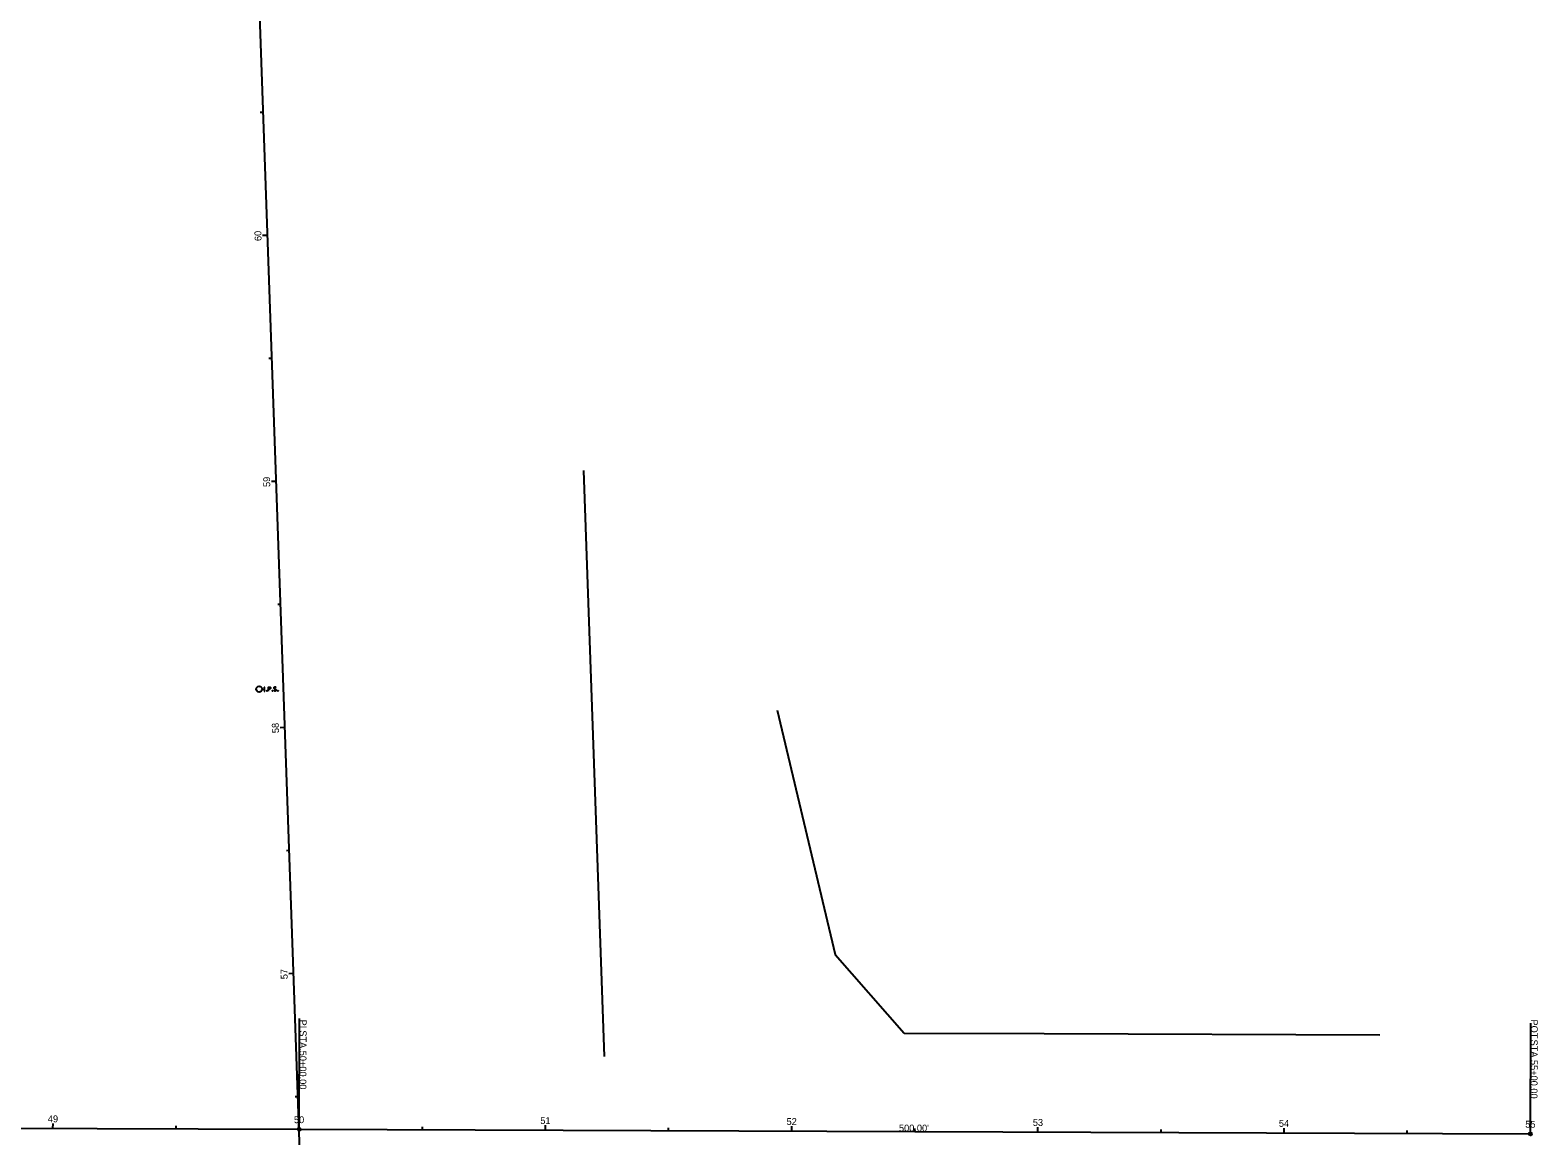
# Model space of a CAD drawing. Extents: x 146022 to 147490, y 436269 to 440659.
# Drawn here: x 146878 to 147490, y 438626 to 439075 of the extents above; entities that cross this region are included whole.
import ezdxf

# ---------------------------------------------------------------- set-up
doc = ezdxf.new("R2010")
doc.units = 0
for name, color, linetype in [('GE_X_Alignment', 7, 'Continuous'), ('GE_X_Alignment_100_Cardinal_Points', 7, 'Continuous'), ('GE_X_Alignment_100_Distances', 7, 'Continuous'), ('GE_X_Alignment_100_Stations', 7, 'Continuous'), ('RW_X_CL', 7, 'Continuous'), ('RW_X_CL_100_Stations', 7, 'Continuous'), ('RW_X_Esmt_SH', 7, 'Continuous'), ('RW_X_Fee_WL', 7, 'Continuous'), ('SV_P_Mon_Cells_Set', 7, 'Continuous')]:
    doc.layers.add(name, color=color, linetype=linetype)

msp = doc.modelspace()

# ---------------------------------------------------------------- linework, layer by layer
at = {"layer": 'GE_X_Alignment'}
for p, q in [((146487.13, 438630.33), (146987.13, 438628.49)), ((146987.13, 438628.49), (147487.13, 438626.65))]:
    msp.add_line(p, q, dxfattribs=at)
at = {"layer": 'GE_X_Alignment_100_Cardinal_Points'}
for p, q in [((146987.13, 438628.49), (146987.3, 438673.49)), ((147487.13, 438626.65), (147487.29, 438671.64))]:
    msp.add_line(p, q, dxfattribs=at)
for centre in [(146987.13, 438628.49), (147487.13, 438626.65)]:
    msp.add_circle(centre, 0.6, dxfattribs=at)
at = {"layer": 'GE_X_Alignment_100_Stations'}
for p, q in [((146887.13, 438628.86), (146887.14, 438630.86)), ((146937.13, 438628.67), (146937.13, 438629.87)), ((146987.13, 438628.49), (146987.14, 438630.49)), ((147037.13, 438628.3), (147037.13, 438629.5)), ((147087.13, 438628.12), (147087.14, 438630.12)), ((147137.13, 438627.93), (147137.13, 438629.13)), ((147187.13, 438627.75), (147187.14, 438629.75)), ((147287.13, 438627.38), (147287.13, 438629.38)), ((147387.13, 438627.01), (147387.13, 438629.01)), ((147237.13, 438627.57), (147237.13, 438628.77)), ((147337.13, 438627.2), (147337.13, 438628.4)), ((147437.13, 438626.83), (147437.13, 438628.03)), ((147487.13, 438626.65), (147487.13, 438628.65))]:
    msp.add_line(p, q, dxfattribs=at)
at = {"layer": 'RW_X_CL'}
msp.add_line((147030.73, 437397.38), (146946.25, 439782.71), dxfattribs=at)
at = {"layer": 'RW_X_CL_100_Stations'}
for p, q in [((146972.5, 439041.5), (146971.3, 439041.46)), ((146974.27, 438991.53), (146972.27, 438991.46)), ((146976.04, 438941.56), (146974.84, 438941.52)), ((146977.81, 438891.59), (146975.81, 438891.52)), ((146979.58, 438841.62), (146978.38, 438841.58)), ((146981.35, 438791.66), (146979.35, 438791.58)), ((146983.12, 438741.69), (146981.92, 438741.64)), ((146984.89, 438691.72), (146982.89, 438691.65)), ((146986.66, 438641.75), (146985.46, 438641.71))]:
    msp.add_line(p, q, dxfattribs=at)
at = {"layer": 'RW_X_Esmt_SH'}
for p, q in [((147181.23, 438798.73), (147204.75, 438699.5)), ((147204.75, 438699.5), (147232.84, 438667.58)), ((147232.84, 438667.58), (147289.66, 438667.37)), ((147289.66, 438667.37), (147426.01, 438666.87))]:
    msp.add_line(p, q, dxfattribs=at)
at = {"layer": 'RW_X_Fee_WL'}
msp.add_line((147111.16, 438658.03), (147102.73, 438896.02), dxfattribs=at)
at = {"layer": 'SV_P_Mon_Cells_Set'}
for points in [[(146972.87, 438808.08), (146973.22, 438808.08)], [(146972.87, 438806.48), (146973.22, 438806.48)], [(146973.04, 438806.48), (146973.04, 438808.08)], [(146974, 438806.7), (146974.06, 438806.7), (146974.09, 438806.67), (146974.12, 438806.62), (146974.12, 438806.56), (146974.09, 438806.51), (146974.06, 438806.48), (146974, 438806.48), (146973.97, 438806.51), (146973.94, 438806.56), (146973.94, 438806.62), (146973.97, 438806.67), (146974, 438806.7)], [(146974.61, 438806.48), (146974.61, 438808.08), (146975.14, 438808.08), (146975.19, 438808.07), (146975.27, 438808.05), (146975.3, 438808.02), (146975.34, 438808), (146975.38, 438807.93), (146975.41, 438807.87), (146975.44, 438807.77), (146975.44, 438807.62), (146975.42, 438807.57), (146975.4, 438807.49), (146975.36, 438807.4), (146975.31, 438807.37), (146975.28, 438807.34), (146975.23, 438807.32), (146975.14, 438807.3), (146974.61, 438807.3)], [(146976.25, 438806.7), (146976.31, 438806.7), (146976.34, 438806.67), (146976.37, 438806.62), (146976.37, 438806.56), (146976.34, 438806.51), (146976.31, 438806.48), (146976.25, 438806.48), (146976.22, 438806.51), (146976.18, 438806.56), (146976.18, 438806.62), (146976.22, 438806.67), (146976.25, 438806.7)], [(146977.62, 438807.97), (146977.6, 438808), (146977.56, 438808.02), (146977.46, 438808.06), (146977.34, 438808.08), (146977.25, 438808.08), (146977.22, 438808.08), (146977.08, 438808.05), (146976.96, 438807.97), (146976.88, 438807.87), (146976.86, 438807.77), (146976.86, 438807.69), (146976.88, 438807.59), (146976.97, 438807.5), (146977.57, 438807.13), (146977.63, 438807.08), (146977.65, 438807.03), (146977.67, 438806.95), (146977.67, 438806.87), (146977.66, 438806.8), (146977.65, 438806.75), (146977.63, 438806.69), (146977.61, 438806.64), (146977.58, 438806.6), (146977.55, 438806.56), (146977.52, 438806.53), (146977.47, 438806.51), (146977.44, 438806.5), (146977.34, 438806.48), (146977.19, 438806.48), (146977.09, 438806.51), (146976.95, 438806.6), (146976.86, 438806.67)], [(146978.43, 438806.7), (146978.49, 438806.7), (146978.52, 438806.67), (146978.55, 438806.62), (146978.55, 438806.56), (146978.52, 438806.51), (146978.49, 438806.48), (146978.43, 438806.48), (146978.4, 438806.51), (146978.37, 438806.56), (146978.37, 438806.62), (146978.4, 438806.67), (146978.43, 438806.7)]]:
    msp.add_lwpolyline(points, dxfattribs=at)
msp.add_circle((146970.85, 438807.28), 1.2, dxfattribs=at)

# ---------------------------------------------------------------- texts
at = {"layer": 'GE_X_Alignment_100_Cardinal_Points'}
for s, p in [('PI', (146987.33, 438673.07)), ('POT', (147487.33, 438673.13)), (' STA. ', (146987.32, 438669.75)), ('50+00.00', (146987.28, 438660.42)), (' STA. ', (147487.31, 438666)), ('55+00.00', (147487.27, 438656.68))]:
    msp.add_text(s, height=2.8, rotation=269.78888, dxfattribs=at).set_placement(p)
at = {"layer": 'GE_X_Alignment_100_Distances'}
msp.add_text("500.00'", height=2.8, rotation=359.78888, dxfattribs=at).set_placement((147230.69, 438627.63))
at = {"layer": 'GE_X_Alignment_100_Stations'}
for s, p in [('49', (146885.03, 438631.36)), ('50', (146984.99, 438631)), ('51', (147085.03, 438630.63)), ('52', (147185.04, 438630.26)), ('53', (147285.06, 438629.89)), ('54', (147384.97, 438629.52)), ('55', (147485.05, 438629.15))]:
    msp.add_text(s, height=2.8, rotation=359.78888, dxfattribs=at).set_placement(p)
at = {"layer": 'RW_X_CL_100_Stations'}
for s, p in [('60', (146971.85, 438989.29)), ('59', (146975.39, 438889.4)), ('58', (146978.93, 438789.44)), ('57', (146982.47, 438689.51))]:
    msp.add_text(s, height=2.8, rotation=92.02828, dxfattribs=at).set_placement(p)

doc.saveas('drawing.dxf')
